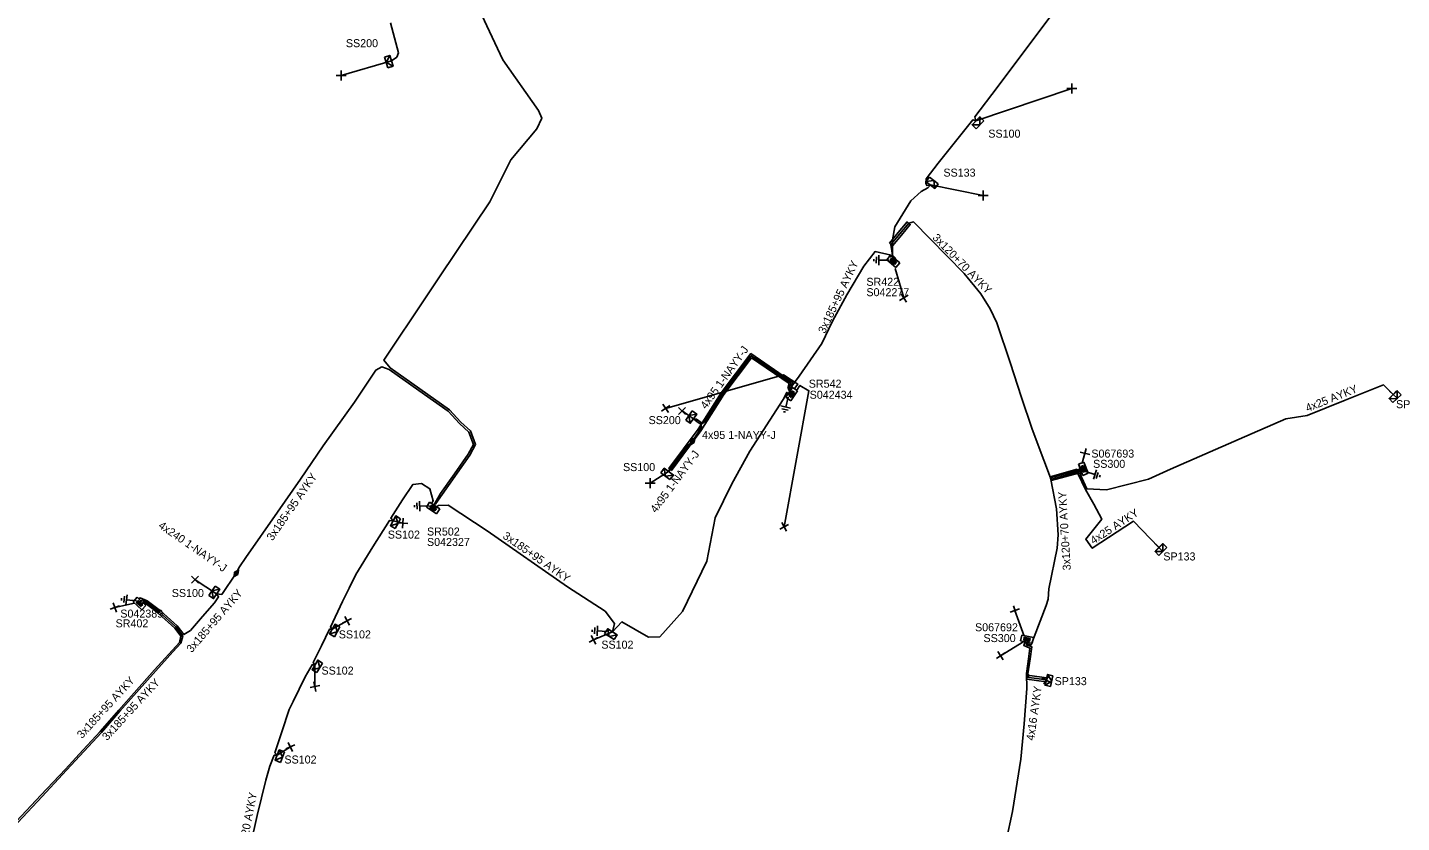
# Model space of a CAD drawing. Extents: x -748492 to -735633, y -1146251 to -1139940.
# Drawn here: x -736584.4 to -736412.8, y -1145296.5 to -1145197.1 of the extents above; entities that cross this region are included whole.
import ezdxf

# ---------------------------------------------------------------- set-up
doc = ezdxf.new("R2010")
doc.units = 0
for name, color, linetype in [('Vrstva 1', 7, 'Continuous'), ('Vrstva 14', 7, 'Continuous'), ('Vrstva 15', 7, 'Continuous'), ('Vrstva 19', 7, 'Continuous'), ('Vrstva 20', 7, 'Continuous'), ('Vrstva 28', 7, 'Continuous'), ('Vrstva 29', 7, 'Continuous'), ('Vrstva 30', 7, 'Continuous'), ('Vrstva 31', 7, 'Continuous'), ('Vrstva 33', 7, 'Continuous'), ('Vrstva 34', 7, 'Continuous'), ('Vrstva 4', 7, 'Continuous'), ('Vrstva 5', 7, 'Continuous'), ('Vrstva 52', 7, 'Continuous'), ('Vrstva 54', 7, 'Continuous'), ('Vrstva 59', 7, 'Continuous'), ('Vrstva 6', 7, 'Continuous'), ('Vrstva 8', 7, 'Continuous'), ('Vrstva 9', 7, 'Continuous')]:
    doc.layers.add(name, color=color, linetype=linetype)

# ---------------------------------------------------------------- blocks, each defined once
blk = doc.blocks.new('NN870')
at = {"layer": 'Vrstva 4'}
for points in [[(0, -0.25), (0.5, 0), (0, 0.25), (-0.5, 0), (0, -0.25)], [(0.37, 0), (0, 0.19), (-0.36, 0), (0, -0.19), (0.37, 0)], [(0.24, 0), (0, 0.12), (-0.25, 0), (0, -0.12), (0.24, 0)], [(0.12, 0), (0, 0.06), (-0.13, 0), (0, -0.06), (0.12, 0)]]:
    blk.add_lwpolyline(points, dxfattribs=at)
blk = doc.blocks.new('NN800')
at = {"layer": 'Vrstva 1'}
for points in [[(-0.44, 0.44), (0.44, -0.44)], [(-0.44, -0.44), (0.44, 0.44)]]:
    blk.add_lwpolyline(points, dxfattribs=at)
blk = doc.blocks.new('NN620')
at = {"layer": 'Vrstva 8'}
for points in [[(0.75, 0), (-0.75, 0)], [(-0.75, 0), (-0.75, -0.75)], [(0.75, -0.75), (0.75, 0)], [(-0.75, -0.75), (0.75, -0.75)], [(0.37, -0.18), (-0.38, -0.18)], [(-0.38, -0.18), (-0.38, -0.56)], [(-0.38, -0.56), (0.37, -0.56)], [(0.32, -0.23), (-0.33, -0.23)], [(-0.33, -0.23), (-0.33, -0.51)], [(-0.33, -0.51), (0.32, -0.51)], [(0.27, -0.27), (-0.28, -0.27)], [(-0.28, -0.27), (-0.28, -0.46)], [(-0.28, -0.46), (0.27, -0.46)], [(0.23, -0.32), (-0.23, -0.32)], [(-0.23, -0.32), (-0.23, -0.42)], [(-0.23, -0.42), (0.23, -0.42)], [(-0.19, -0.37), (0.19, -0.37)], [(0.23, -0.42), (0.23, -0.32)], [(0.27, -0.46), (0.27, -0.27)], [(0.32, -0.51), (0.32, -0.23)], [(0.37, -0.56), (0.37, -0.18)]]:
    blk.add_lwpolyline(points, dxfattribs=at)
blk = doc.blocks.new('NN630')
at = {"layer": 'Vrstva 9'}
for points in [[(0, -0.7), (-0.7, 0)], [(-0.7, -0.7), (-0.7, 0), (0.7, 0), (0.7, -0.7)], [(-0.7, -0.7), (0.7, -0.7)], [(0, -0.7), (0.7, 0)]]:
    blk.add_lwpolyline(points, dxfattribs=at)
blk = doc.blocks.new('NN810')
at = {"layer": 'Vrstva 14'}
for points in [[(0, -0.64), (0, -1.89)], [(0.63, -1.89), (-0.62, -1.89)], [(0.39, -2.2), (-0.4, -2.2)], [(0, -2.52), (-0.12, -2.52)], [(0.14, -2.52), (0, -2.52)]]:
    blk.add_lwpolyline(points, dxfattribs=at)

msp = doc.modelspace()

# ---------------------------------------------------------------- linework, layer by layer
at = {"layer": 'Vrstva 20'}
for points in [[(-736476.77, -1145224.1), (-736475.67, -1145222.76), (-736474.56, -1145221.42), (-736474.18, -1145221.74), (-736475.28, -1145223.08), (-736476.39, -1145224.42)], [(-736489.48, -1145242.26), (-736489.3, -1145241.63), (-736494, -1145238.41), (-736497.45, -1145242.99), (-736500.34, -1145247.54), (-736504, -1145252.47), (-736504.32, -1145252.24), (-736500.68, -1145247.32), (-736497.78, -1145242.77), (-736494.08, -1145237.87), (-736488.84, -1145241.47), (-736489.09, -1145242.37)], [(-736453.31, -1145252.32), (-736453.17, -1145252.8), (-736456.56, -1145253.74), (-736456.7, -1145253.26)], [(-736459.54, -1145278.05), (-736457.15, -1145278.39), (-736457.21, -1145278.89), (-736459.6, -1145278.55)]]:
    msp.add_lwpolyline(points, close=True, dxfattribs=at)
at = {"layer": 'Vrstva 5'}
for points in [[(-736529.35, -1145192.01), (-736525.08, -1145201.16), (-736520.61, -1145207.5), (-736520.2, -1145208.47), (-736520.82, -1145209.81), (-736524.06, -1145213.67), (-736526.69, -1145218.9), (-736532.96, -1145228.28), (-736534.65, -1145230.77), (-736539.92, -1145238.71), (-736539.12, -1145239.66), (-736531.71, -1145244.9), (-736530.3, -1145246.45), (-736529.11, -1145247.53), (-736528.48, -1145249.25), (-736529.17, -1145250.57), (-736532.65, -1145255.5), (-736533.51, -1145256.75)], [(-736456.35, -1145195.33), (-736463.31, -1145204.63), (-736466.12, -1145208.32), (-736465.96, -1145208.8), (-736466.37, -1145208.68), (-736470.67, -1145214.11), (-736472.18, -1145216.05), (-736472.22, -1145216.58), (-736472.1, -1145216.9), (-736471.66, -1145216.81), (-736471.98, -1145217.19), (-736472.8, -1145217.64), (-736474.08, -1145218.81), (-736476.08, -1145222.04), (-736476.41, -1145223.65), (-736476.4, -1145225.6), (-736475.98, -1145225.98)], [(-736452.95, -1145252.22), (-736453.28, -1145252.47), (-736456.67, -1145253.42), (-736457.49, -1145251.19), (-736458.95, -1145247.34), (-736460.31, -1145243.23), (-736461.66, -1145239.12), (-736463.37, -1145234.04), (-736464.21, -1145232.3), (-736465.35, -1145230.43), (-736467.44, -1145227.89), (-736469.58, -1145225.7), (-736473.76, -1145221.42), (-736474.37, -1145221.58), (-736476.58, -1145224.26), (-736476.4, -1145225.6), (-736476.24, -1145225.95)], [(-736488.96, -1145242.28), (-736488.95, -1145241.95), (-736488.05, -1145240.68), (-736485.2, -1145236.62), (-736483.88, -1145233.84), (-736482.1, -1145230.55), (-736479.98, -1145226.96), (-736478.56, -1145225.14), (-736476.57, -1145225.58), (-736476.66, -1145225.88)], [(-736501.25, -1145246.01), (-736500.89, -1145246.06), (-736500.13, -1145246.62), (-736499.87, -1145246.42), (-736497.62, -1145242.88), (-736494.04, -1145238.14), (-736489.07, -1145241.55), (-736489.35, -1145242.4), (-736489.21, -1145242.6)], [(-736533.67, -1145256.81), (-736532.87, -1145255.37), (-736531.12, -1145252.91), (-736529.38, -1145250.45), (-736528.75, -1145249.23), (-736529.33, -1145247.68), (-736530.48, -1145246.63), (-736531.88, -1145245.09), (-736535.57, -1145242.48), (-736539.25, -1145239.87), (-736540.2, -1145239.52), (-736540.93, -1145239.93), (-736543.59, -1145243.94), (-736547.5, -1145249.41), (-736550.36, -1145253.55), (-736553.22, -1145257.69), (-736557.16, -1145263.34), (-736557.98, -1145264.52), (-736558.36, -1145265.33)], [(-736533.28, -1145257.04), (-736533.13, -1145256.84), (-736531.9, -1145256.81), (-736527.01, -1145260.02), (-736516.99, -1145267.02), (-736512.3, -1145270.07), (-736511.1, -1145271.61), (-736511.38, -1145272.63), (-736510.19, -1145271.39), (-736506.88, -1145273.32), (-736505.47, -1145273.26), (-736502.63, -1145270.09), (-736499.58, -1145263.8), (-736498.55, -1145258.39), (-736496.47, -1145254.13), (-736494.21, -1145250.05), (-736490.04, -1145243.63), (-736489.6, -1145242.73), (-736489.4, -1145242.89)], [(-736501.25, -1145246.01), (-736500.79, -1145246.41), (-736500.31, -1145246.74), (-736500.23, -1145247.08), (-736500.75, -1145247.87), (-736501.36, -1145248.84)], [(-736504.36, -1145252.62), (-736501.84, -1145249.23), (-736501.36, -1145248.84)], [(-736459.47, -1145273.95), (-736459.47, -1145274.16), (-736459.07, -1145274.28), (-736458.71, -1145273.27), (-736457.21, -1145269.33), (-736456.95, -1145268.55), (-736456.86, -1145267.28), (-736455.84, -1145262.17), (-736455.68, -1145260.54), (-736455.89, -1145257.29), (-736456.62, -1145253.6), (-736453.2, -1145252.65), (-736452.9, -1145252.4)], [(-736556.56, -1145299.13), (-736555.74, -1145295.59), (-736554.69, -1145291.17), (-736554.16, -1145289.43), (-736553.63, -1145288.05), (-736553.25, -1145288.04), (-736553.53, -1145287.77), (-736552.67, -1145285.12), (-736551.77, -1145282.36), (-736551.27, -1145281.33), (-736549.74, -1145278.25), (-736548.9, -1145276.75), (-736548.54, -1145276.78), (-736548.76, -1145276.49), (-736547.73, -1145274.39), (-736546.72, -1145272.32), (-736546.37, -1145272.29), (-736546.59, -1145272.05), (-736545.1, -1145268.87), (-736544.27, -1145267.17), (-736543.43, -1145265.47), (-736541.29, -1145262.03), (-736539.23, -1145258.71), (-736538.78, -1145258.78), (-736539.07, -1145258.45), (-736537.62, -1145256.16), (-736536.32, -1145254.25), (-736535.24, -1145254.09), (-736534.2, -1145254.76), (-736533.75, -1145256.26), (-736533.97, -1145256.62)], [(-736558.36, -1145265.33), (-736560.18, -1145267.97), (-736560.82, -1145267.9)], [(-736560.82, -1145267.9), (-736560.58, -1145268.27), (-736561.09, -1145269), (-736562.6, -1145270.74), (-736564.1, -1145272.49), (-736564.91, -1145272.99), (-736565.76, -1145271.9), (-736567.82, -1145270.02), (-736569.51, -1145268.75), (-736570.39, -1145268.4), (-736570.52, -1145268.53)], [(-736570.03, -1145268.99), (-736569.94, -1145268.91), (-736568.91, -1145269.7), (-736568.07, -1145270.33), (-736566.05, -1145272.17), (-736565.28, -1145273.17), (-736565.46, -1145273.96), (-736568.56, -1145277.39), (-736573.04, -1145282.43), (-736575.36, -1145285.07), (-736577.54, -1145287.44), (-736579.71, -1145289.8), (-736582.76, -1145293.05), (-736585.8, -1145296.3)], [(-736570.25, -1145268.78), (-736570.12, -1145268.66), (-736569.63, -1145268.91), (-736567.95, -1145270.17), (-736565.91, -1145272.03), (-736565.02, -1145273.18), (-736565.28, -1145274.06), (-736566.27, -1145275.13), (-736568.42, -1145277.53), (-736572.89, -1145282.57), (-736575.22, -1145285.21), (-736579.57, -1145289.94), (-736582.61, -1145293.19), (-736585.66, -1145296.44)], [(-736462.2, -1145298.75), (-736461.39, -1145295.09), (-736460.34, -1145288.55), (-736459.96, -1145284.14), (-736459.59, -1145279.73), (-736459.67, -1145277.85), (-736459.41, -1145276.01), (-736459.22, -1145274.66), (-736459.99, -1145274.36), (-736459.83, -1145273.88)]]:
    msp.add_lwpolyline(points, dxfattribs=at)
at = {"layer": 'Vrstva 52'}
for points in [[(-736539.11, -1145196.55), (-736538.09, -1145200.31), (-736538.31, -1145200.86), (-736538.99, -1145201.3)], [(-736452.76, -1145252.74), (-736452.95, -1145252.94), (-736452.1, -1145254.78), (-736449.67, -1145254.89), (-736444.42, -1145253.55), (-736441.66, -1145252.31), (-736433.08, -1145248.56), (-736427.25, -1145246.05), (-736424.61, -1145245.6), (-736419.83, -1145243.7), (-736415.04, -1145241.79), (-736413.84, -1145243)], [(-736452.82, -1145252.54), (-736453.18, -1145252.95), (-736452.28, -1145254.86), (-736451.22, -1145256.69), (-736450.25, -1145258.55), (-736451.24, -1145259.8), (-736452.24, -1145261.05), (-736451.44, -1145262.2), (-736446.27, -1145258.83), (-736443.1, -1145262.1)], [(-736459.68, -1145273.94), (-736459.67, -1145274.27), (-736459, -1145274.51), (-736459.21, -1145276.03), (-736459.47, -1145277.87), (-736459.36, -1145278.33), (-736458.38, -1145278.47), (-736457.18, -1145278.64)]]:
    msp.add_lwpolyline(points, dxfattribs=at)
at = {"layer": 'Vrstva 59'}
for points in [[(-736538.99, -1145201.3), (-736545.25, -1145203.13)], [(-736465.96, -1145208.8), (-736454, -1145204.75)], [(-736471.66, -1145216.81), (-736465.06, -1145218.13)], [(-736476.04, -1145227.24), (-736474.97, -1145230.92)], [(-736488.65, -1145242.25), (-736488.22, -1145241.69), (-736489.99, -1145240.52), (-736504.73, -1145244.72)], [(-736488.36, -1145242.45), (-736487.95, -1145241.85), (-736486.84, -1145242.53), (-736489.93, -1145259.53)], [(-736501.25, -1145246.01), (-736502.67, -1145245.05)], [(-736452.69, -1145251.58), (-736452.36, -1145250.33)], [(-736504.36, -1145252.62), (-736506.65, -1145254.05)], [(-736538.78, -1145258.78), (-736537.54, -1145259.08)], [(-736560.82, -1145267.9), (-736563.52, -1145266.14)], [(-736571.08, -1145269.04), (-736573.55, -1145269.61)], [(-736546.37, -1145272.29), (-736544.52, -1145271.27)], [(-736459.95, -1145273.19), (-736461.1, -1145269.97)], [(-736511.38, -1145272.63), (-736513.74, -1145273.64)], [(-736460, -1145273.84), (-736462.89, -1145275.62)], [(-736548.54, -1145276.78), (-736548.54, -1145279.48)], [(-736553.25, -1145288.04), (-736551.6, -1145287.01)]]:
    msp.add_lwpolyline(points, dxfattribs=at)

# ---------------------------------------------------------------- block references
at = {"layer": 'Vrstva 15'}
for p, rotation in [((-736476.21, -1145226.21), -90.33324168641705), ((-736489.29, -1145242.72), -13.52826659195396), ((-736452.9, -1145252.4), 71.83402783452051), ((-736533.58, -1145256.86), -88.12216107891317), ((-736570.2, -1145268.83), -96.00904723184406), ((-736511.38, -1145272.63), -93.094036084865)]:
    msp.add_blockref('NN810', p, dxfattribs=dict(at, rotation=rotation))
at = {"layer": 'Vrstva 19'}
for p, rotation in [((-736501.36, -1145248.84), 57.29769284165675), ((-736558.36, -1145265.33), -124.58214423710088)]:
    msp.add_blockref('NN870', p, dxfattribs=dict(at, rotation=rotation))
at = {"layer": 'Vrstva 28'}
for p, rotation in [((-736476.06, -1145226.08), -39.601388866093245), ((-736489.29, -1145242.72), 55.669686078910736), ((-736452.9, -1145252.4), 111.46772776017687), ((-736533.58, -1145256.86), -33.10027783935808), ((-736570.2, -1145268.83), -42.72153062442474), ((-736459.68, -1145273.94), 167.6428888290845)]:
    msp.add_blockref('NN620', p, dxfattribs=dict(at, rotation=rotation))
at = {"layer": 'Vrstva 31'}
for p, rotation in [((-736538.99, -1145201.3), -72.52406111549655), ((-736465.96, -1145208.8), 45.57268058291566), ((-736471.66, -1145216.81), 141.89330276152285), ((-736413.84, -1145243), 43.152327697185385), ((-736501.25, -1145246.01), -124.84573320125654), ((-736504.33, -1145252.63), -36.54001121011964), ((-736538.78, -1145258.78), 61.288738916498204), ((-736443.1, -1145262.1), 44.83284728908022), ((-736560.82, -1145267.9), -123.69006748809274), ((-736546.37, -1145272.29), 60.255019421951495), ((-736511.38, -1145272.63), -33.20278335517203), ((-736548.54, -1145276.78), 59.39360551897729), ((-736457.18, -1145278.64), 76.98298612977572), ((-736553.25, -1145288.04), 68.5144388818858)]:
    msp.add_blockref('NN630', p, dxfattribs=dict(at, rotation=rotation))
at = {"layer": 'Vrstva 34'}
for p, rotation in [((-736545.25, -1145203.13), 45), ((-736454, -1145204.75), 45), ((-736465.06, -1145218.13), 45), ((-736474.97, -1145230.92), -12.74116387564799), ((-736413.84, -1145243), -176.9334915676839), ((-736504.73, -1145244.72), 168.98282516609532), ((-736452.36, -1145250.33), 120.71273332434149), ((-736506.65, -1145254.05), 45), ((-736537.54, -1145259.08), 131.38608894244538), ((-736489.93, -1145259.53), 163.73990271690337), ((-736443.1, -1145262.1), 177.7975139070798), ((-736573.55, -1145269.61), -25.641005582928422), ((-736461.1, -1145269.97), 152.96268055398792), ((-736544.52, -1145271.27), 161.90954174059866), ((-736513.74, -1145273.64), 163.2495944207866), ((-736462.89, -1145275.62), 167.905224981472), ((-736457.18, -1145278.64), -164.7448584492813), ((-736548.54, -1145279.48), 147.3806750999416), ((-736551.6, -1145287.01), 160.14477217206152)]:
    msp.add_blockref('NN800', p, dxfattribs=dict(at, rotation=rotation))
for p in [(-736502.67, -1145245.05), (-736563.52, -1145266.14)]:
    msp.add_blockref('NN800', p, dxfattribs=at)

# ---------------------------------------------------------------- texts
at = {"layer": 'Vrstva 29'}
for s, p in [('S042277', (-736479.65, -1145230.71)), ('S042434', (-736486.74, -1145243.52)), ('S067693', (-736451.55, -1145250.87)), ('S042327', (-736534.54, -1145261.91)), ('S042389', (-736572.85, -1145270.86)), ('S067692', (-736466.08, -1145272.57))]:
    msp.add_text(s, height=1, dxfattribs=at).set_placement(p)
at = {"layer": 'Vrstva 30'}
for s, p in [('SR422', (-736479.65, -1145229.41)), ('SR542', (-736486.85, -1145242.14)), ('SS300', (-736451.33, -1145252.15)), ('SR502', (-736534.54, -1145260.61)), ('SR402', (-736573.44, -1145272.08)), ('SS300', (-736465.02, -1145273.92))]:
    msp.add_text(s, height=1, dxfattribs=at).set_placement(p)
at = {"layer": 'Vrstva 33'}
for s, p in [('SS200', (-736544.67, -1145199.6)), ('SS100', (-736464.42, -1145210.9)), ('SS133', (-736470.03, -1145215.77)), ('SP133', (-736413.49, -1145244.7)), ('SS200', (-736506.86, -1145246.69)), ('SS100', (-736510.05, -1145252.56)), ('SS102', (-736539.44, -1145260.99)), ('SP133', (-736442.56, -1145263.72)), ('SS100', (-736566.42, -1145268.29)), ('SS102', (-736545.56, -1145273.46)), ('SS102', (-736512.76, -1145274.74)), ('SS102', (-736547.72, -1145277.98)), ('SP133', (-736456.14, -1145279.3)), ('SS102', (-736552.35, -1145289.09))]:
    msp.add_text(s, height=1, dxfattribs=at).set_placement(p)
at = {"layer": 'Vrstva 54'}
for s, rotation, p in [('4x25 AYKY', 21.708, (-736424.55, -1145245.19)), ('4x25 AYKY', 33.098, (-736451.28, -1145261.75)), ('4x16 AYKY', 81.957, (-736458.71, -1145286.27))]:
    msp.add_text(s, height=1, rotation=rotation, dxfattribs=at).set_placement(p)
at = {"layer": 'Vrstva 6'}
for s, rotation, p in [('3x120+70 AYKY', 314.357, (-736471.47, -1145223.48)), ('3x185+95 AYKY', 64.601, (-736484.84, -1145235.46)), ('4x95 1-NAYY-J', 54.482, (-736499.67, -1145244.89)), ('4x95 1-NAYY-J', 53.431, (-736505.94, -1145257.86)), ('3x185+95 AYKY', 55.168, (-736553.84, -1145261.34)), ('3x120+70 AYKY', 93.462, (-736454.11, -1145264.93)), ('4x240 1-NAYY-J', 325.418, (-736568.18, -1145259.57)), ('3x185+95 AYKY', 325.062, (-736525.17, -1145260.87)), ('3x185+95 AYKY', 49.221, (-736563.93, -1145275.32)), ('3x185+95 AYKY', 47.41, (-736577.64, -1145286.04)), ('3x185+95 AYKY', 47.396, (-736574.5, -1145286.3)), ('3x240+120 AYKY', 78.873, (-736557.81, -1145303.21))]:
    msp.add_text(s, height=1, rotation=rotation, dxfattribs=at).set_placement(p)
msp.add_text('4x95 1-NAYY-J', height=1, dxfattribs=at).set_placement((-736500.18, -1145248.54))

doc.saveas('drawing.dxf')
